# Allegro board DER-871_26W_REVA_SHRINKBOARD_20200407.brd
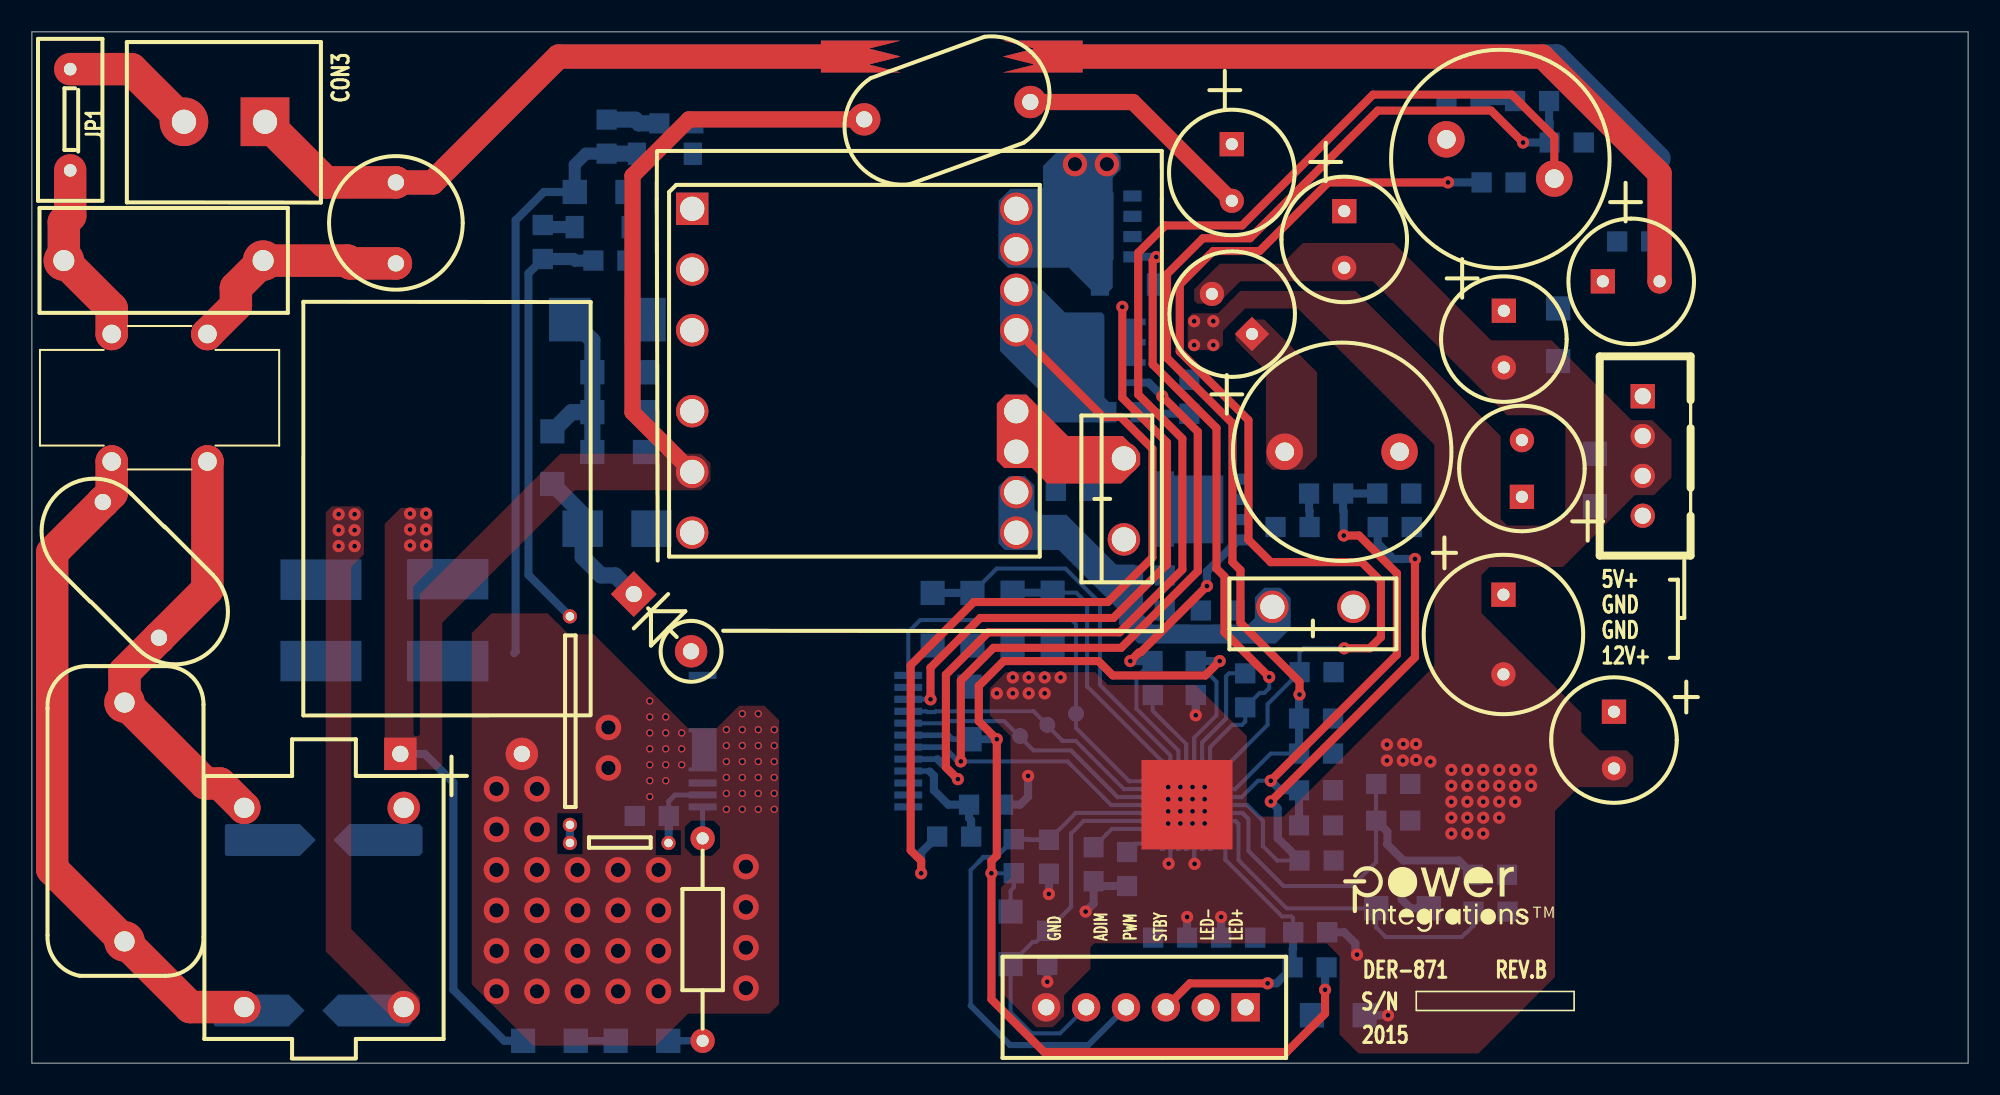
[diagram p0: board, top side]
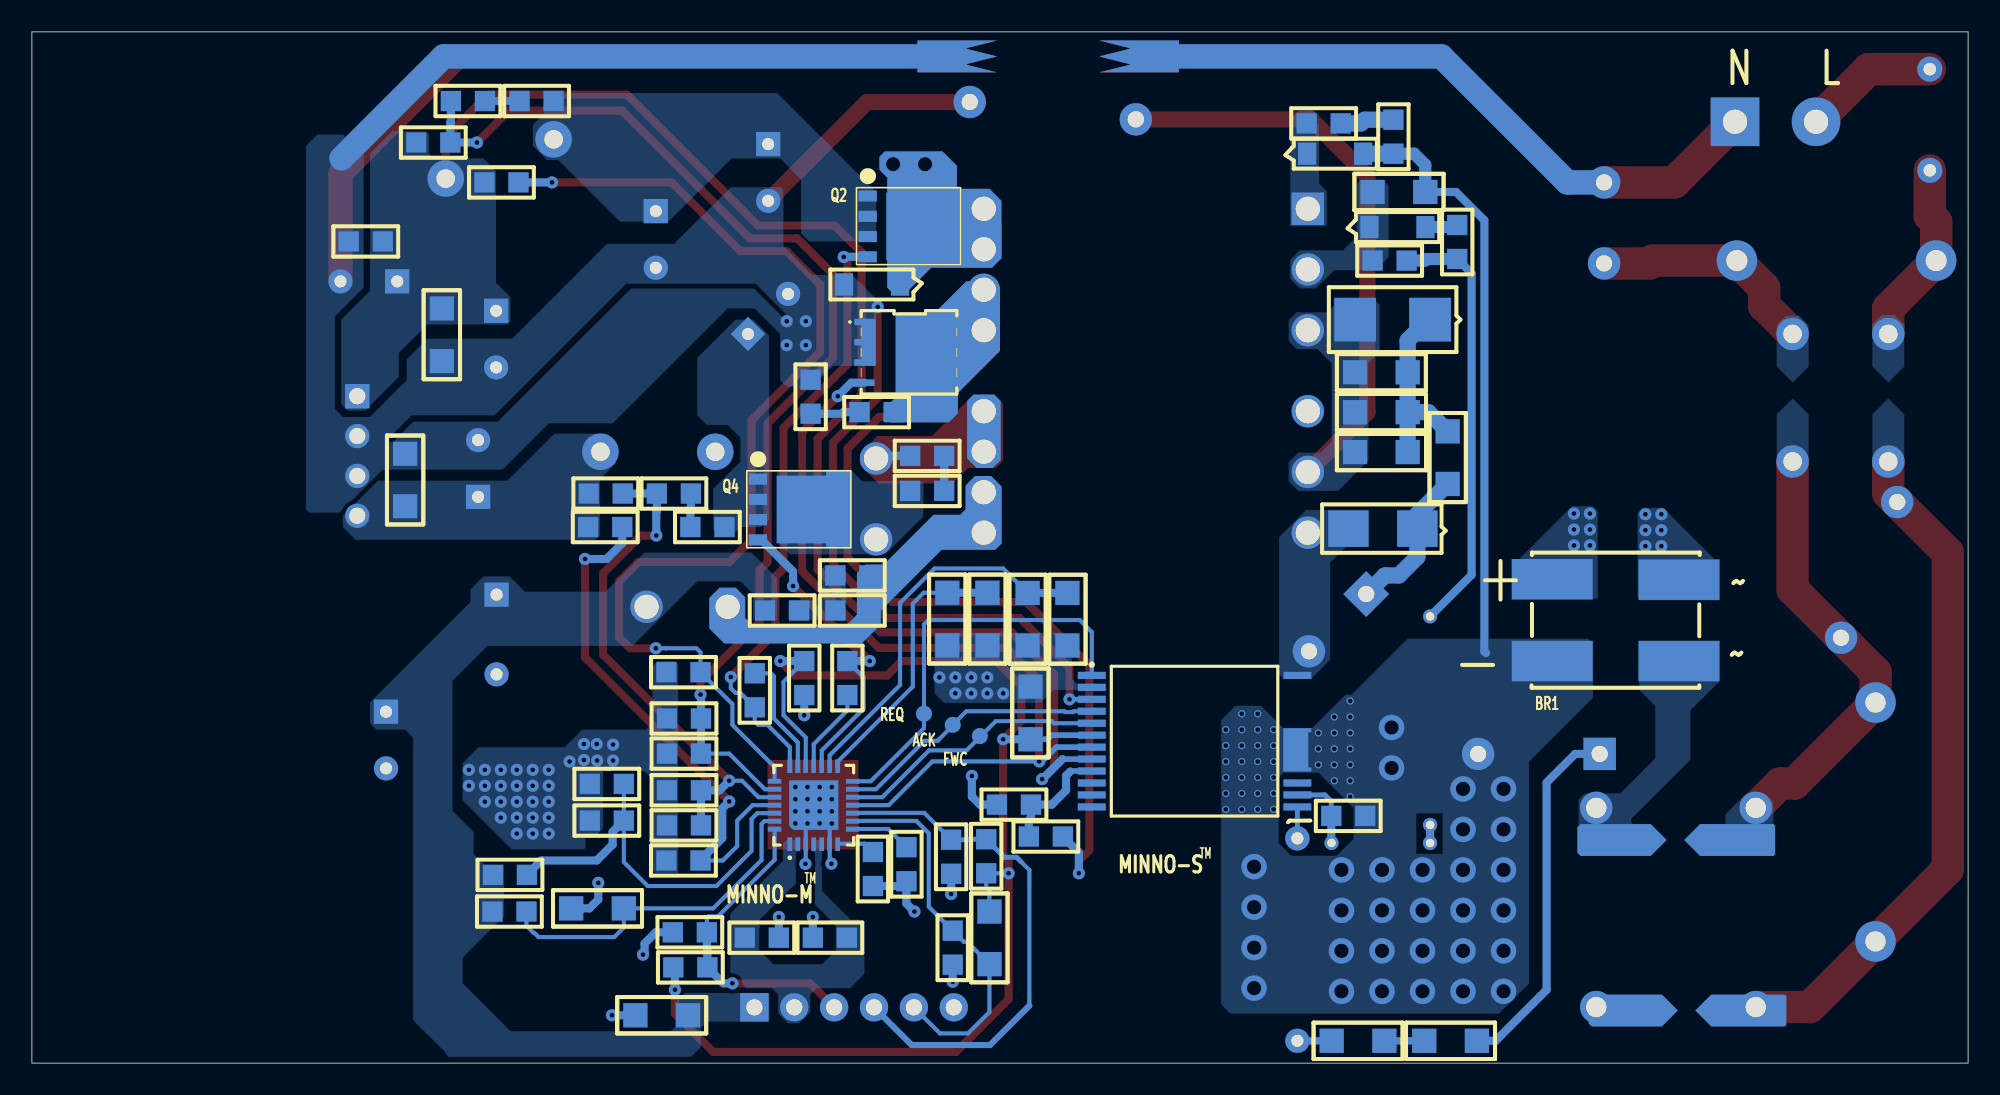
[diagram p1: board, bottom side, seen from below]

Outline 121.4 x 64.7 mm; copper layers: TOP, BOTTOM. Coordinates in mm from the lower left corner of the outline.
Outline path: 0,64.7 0,0 121.4,0 121.4,64.7 0,64.7

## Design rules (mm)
constraint set DEFAULT: min track width 0.1

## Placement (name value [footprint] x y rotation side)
BR1  Z4DGP408L-HF  [PI_SM_D_Z4D]  26.13 30.33 90 bottom
C1  22 uF  [PISMC1206]  37.34 54.65 180 bottom
C2  4.7 uF  [PISMC0805]  39.93 15.51 180 bottom
C3  100 uF  [PIPOLCAPCLYD630LS300040]  23.1 19.4 0 bottom
C4  220 nF  [PISMC0805]  76.08 22.32 90 bottom
C5  220 nF  [PISMC0805]  66.57 11.41 90 bottom
C6  0.47 nF  [PINPYCAPRAD540X290LS400040]  62.6 60.3 200 top
C7  2.2 uF  [PISMC1206]  58.79 20.32 90 bottom
C9  100 pf  [PISMC0805]  73.29 28.4 0 bottom
C10  1000 uF  [PIPOLCAPCLYD320LS140030]  75.24 57.66 270 top
C11  2.2 uF  [PISMC0805]  72.97 25.23 270 bottom
C12  DNF  [PISMC0805]  64.2 35.9 0 bottom
C13  470 uF  [PIPOLCAPCLYD320LS140030]  76.5 45.75 135 top
C14  56 uF  [PIPOLCAPCYLD10D14H5LS030]  92.27 29.39 270 top
C15  120 uF  [PIPOLCAPCLYD320LS140030]  99.2 22.05 270 top
C17  330 nF  [PINPCAPRAD760X380590050]  5.81 22.62 270 top
C18  DNF  [PISMC1206]  38.44 38.34 180 bottom
C19  DNF  [PISMC0805]  72.57 40.74 90 bottom
C25  1000 uF  [PIPOLCAPCLYD320LS140030]  82.28 53.45 270 top
C26  1000 uF  [PIPOLCAPCLYD320LS140030]  92.29 47.2 270 top
C27  470 nF  [PISMC0805]  92.99 60.36 0 bottom
C28  100 nF  [PISMC1206]  95.7 47.35 270 bottom
C29  100 nF  [PISMC1206]  80.26 3 0 bottom
C30  100 nF  [PISMC0805]  79.48 12.71 0 bottom
C31  100 nF  [PISMC0805]  79.48 24.52 0 bottom
C32  DNF  [PISMC0805]  36.04 57.06 90 bottom
C33  220 nF  [PISMC0805]  70.27 25.23 270 bottom
C34  100 nF  [PISMC1206]  98 34.94 90 bottom
C35  680 uF  [PIPOLCAPCLYD320LS140030]  93.42 35.53 90 top
C36  100 nF  [PISMC1206]  84.29 9.71 0 bottom
C37  DNF  [PISMC0805]  58.76 16.22 0 bottom
C38  DNF  [PISMC0805]  76.7 7.87 180 bottom
C39  470 nF  [PISMC0805]  80.08 35.74 0 bottom
C40  DNF  [PISMC0805]  70.3 7.87 0 bottom
C41  DNF  [PINPXCAPRAD610X260492040]  2 50.35 0 top
C44  1000 uF  [PIPOLCAPCLYD320LS140030]  98.5 49.05 0 top
C45  4.7 nF  [PISMC1206]  56.47 26.2 90 bottom
C46  DNF  [PISMC1206]  64 26.21 90 bottom
CON3  TERMINAL BLOCK  [PI_TERM_BLOCK_2PIN]  14.61 59.06 90 top
D1  BAT46W-TP  [PI_SM_SOD-123_12]  41.44 57.06 180 bottom
D2  DNF  [PISMDO214AC12]  34.53 33.53 0 bottom
D3  DST5200  [PIDVT0220ACREVA]  77.78 28.63 0 top
D4  MMSZ5252BT1G  [PI_SM_SOD-123_12]  66.97 48.85 0 bottom
D5  VS-8TQ080PBF  [PIDVT0220ACREVA]  68.47 37.94 270 top
D8  MMSZ5246B-7-F  [PI_SM_SOD-123_12]  37.54 52.45 180 bottom
D9  BYV26C  [PIDV200X150X040SOD57R]  37.74 29.43 315 top
F1  2 A  [PI_TR5_SUBMIN_FUSE]  22.82 55.26 270 top
J1  CON4  [PI_HIROSE_2P5_4POS]  101 41.84 270 top
J2  CON6  [PIHDR6PINDF125MM]  76.1 3.5 90 top
JP2  J  [PI_JUMPER200]  34.83 13.81 0 top
JP3  J  [PI_JUMPER200#2]  33.73 28.03 270 top
L1  6.8 mH  [PIIND4P_21X15MMD040]  13.31 16.02 270 top
L2  10 uH  [PI_CHOKE_H625XD539LS290D046]  88.69 57.96 340 top
L3  10 uH  [PI_CHOKE_H625XD539LS290D046]  78.55 38.36 0 top
L4  1 mH  [PIIND4PKEMET_SC-GS]  5 45.75 270 top
NOREF  -  []  82.24 12.79 0 top
NOREF#2  -  []  104.4 0 90 top
NOREF#3  -  []  0 64.7 0 top
Q1  SQJA62EP-T1_GE3  [PISMPQFN5X6B]  69.2 46.5 270 bottom
Q2  SI4154DY-T1-GE3  [PI_SM_SOT669]  69 54.4 270 bottom
Q4  SI4154DY-T1-GE3  [PI_SM_SOT669]  75.88 36.64 270 bottom
R1  10  [PISMR1206]  32.63 36.34 90 bottom
R2  DNF  [PISMR1206]  38.44 40.84 180 bottom
R3  9.1 k  [PISMR0805]  68.67 11.11 90 bottom
R4  10 k  [PISMR1206]  58.97 26.2 90 bottom
R5  47  [PISMR0805]  56.76 14.21 0 bottom
R6  DNF  [PISMR0805]  67.37 40.84 0 bottom
R7  120 k  [PISMR0805]  92.49 11.81 180 bottom
R8  3.3 k  [PISMR0805]  84.29 15.22 0 bottom
R9  10 k  [PISMR0805]  88.69 60.36 0 bottom
R10  3.3 k  [PISMR0805]  81.58 19.42 180 bottom
R11  2.00 M  [PISMR1206]  36.6 1.4 0 bottom
R12  10  [PIRAD400X175LS250031]  2.4 62.36 270 top
R13  22  [PISMR0805]  68.89 28.4 0 bottom
R14  10 k  [PISMR0805]  37.34 50.35 180 bottom
R15  DNF  [PISMR0805]  66.33 38.1 180 bottom
R16  2.00 M  [PISMR1206]  30.8 1.4 0 bottom
R17  100 k  [PISMR0805]  63.76 14.01 270 bottom
R19  100 k  [PISMR0805]  79.08 8.21 0 bottom
R22  100 k  [PISMR0805]  63.66 8.31 270 bottom
R29  DNF  [PISMR0805]  61.56 11.91 90 bottom
R35  10 k  [PISMR0805]  97.3 57.76 180 bottom
R37  47  [PISMR0805]  32.03 50.45 90 bottom
R39  DNF  [PISMR0805]  39.34 58.96 0 bottom
R40  39 k  [PISMR1206]  61.49 26.21 90 bottom
R41  3.9 k  [PISMR0805]  81.58 17.12 180 bottom
R42  33 k  [PISMR0805]  86.49 35.74 180 bottom
R44  33 k  [PISMR0805]  77.98 33.63 0 bottom
R46  DNF  [PISMR0805]  81.18 6.01 180 bottom
R47  10  [PISMR0805]  90.39 9.51 0 bottom
R48  10  [PISMR0805]  90.89 55.26 0 bottom
R49  10  [PISMR0805]  84.38 33.63 0 bottom
R50  DNF  [PISMR1206]  61.36 9.51 270 bottom
R51  4.7 k  [PISMR0805]  99.4 51.55 0 bottom
R52  DNF  [PISMR1206]  38.44 43.34 180 bottom
R53  22  [PISMR0805]  68.89 30.6 0 bottom
R54  68 k  [PISMR0805]  81.58 21.62 180 bottom
R55  68 k  [PISMR0805]  81.58 14.92 180 bottom
R56  220 k  [PISMR0805]  84.29 17.52 0 bottom
R60  0R  [PI14WRESD100LS500D030]  42.06 14.1 270 top
T1  PQ20/16  [PI_BOBBIN_PQ2016_V_14P_8X6A]  41.4 53.6 0 top
U2  MINNO (A)  [PI_IC_INSOP_24D]  54.95 24.33 180 bottom
U3  MINNO (B)  [QFN50P500X500X80-29N]  72.38 16.18 90 bottom
VDR1  275 Vac  [PIDISC500X225LS335X140040]  4.45 35.2 315 top
VR1  SMBJ150A  [PISMDO214AA12]  33.73 46.65 0 bottom

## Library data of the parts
BR1 = DISCRETE BRIDGE_+~~-
C1 C2 C4 C5 C7 C9 C11 C12 C17 C18 C27-C34 C36-C41 C45 C46 = CAP NP
C3 = CAP POL: alternate symbols: (pipolcapd630ls3000401600lhoriz)
C6 = CAP NP: alternate symbols: (pinpycaprad540x290ls400040h,pinpycaprad500x220ls400040)
C10 C25 C44 = CAP POL
C13 C26 = CAP POL: alternate symbols: (pipolcapclyd320ls140030430h)
C14 = CAP POL: alternate symbols: (pipolcapcyld10D14H5LS030H)
C15 = CAP POL: alternate symbols: (pipolcapclyd8X21P5X3P5LS30h)
C19 = CAP NP: alternate symbols: (pismc0805_1)
C35 = CAP POL: alternate symbols: (pipolcapclyd320ls140d30h750)
CON3 = CON2
D1 D4 D8 VR1 = DIODE_ZENER
D2 = DIODE
D3 D5 = DIODE SCHOTTKY
D9 = DIODE: alternate symbols: (pidax425x150040sod57,pidv200x150x040sod57r)
F1 = FUSE
J1 = CON4
J2 = CON6
JP2 JP3 = JUMPER_1
L1 = CMC_ 4P_14_23
L2 L3 = INDUCTOR
L4 = CMC_ 4P_12_43
Q1 = FET_N_SGD_123_4_5678
Q2 Q4 = FET_N_SGD_123_4_5: alternate symbols: (pismso8)
R1-R11 R13-R17 R19 R22 R29 R35 R37 R39-R42 R44 R46-R56 = R
R12 = THERMISTOR: alternate symbols: (pirad400x175ls250040_h)
R60 = R: alternate symbols: (pi14wvresd100ls125d030,pi14wvresd100ls150d030,pi14wvresd100ls200d030,pi14wvresd100ls300d030,pi14wresd100ls400d030,pi14wresd100ls500d030)
T1 = BPQ2016_14P_6-8-GENERIC
U2 = MinnoPriSec: alternate symbols: (pi_ic_insop_24d)
U3 = MINNO_Master_QFN_RevB: alternate symbols: (QFN50P500X500X80-29NTH2)
VDR1 = VARISTOR

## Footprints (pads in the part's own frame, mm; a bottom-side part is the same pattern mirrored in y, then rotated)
PI14WRESD100LS500D030
  round 1.524 hole 0.762: 1(0,0) 2(12.7,0)
PI_BOBBIN_PQ2016_V_14P_8X6A
  rect 2.032x2.032 hole 1.524: 1(0,0)
  round 2.032 hole 1.524: 2(0,-3.81) 3(0,-7.62) 4(0,-12.7) 5(0,-16.51) 6(0,-20.32) 7(20.32,-20.32) 8(20.32,-17.78) 9(20.32,-15.24) 10(20.32,-12.7) 11(20.32,-7.62) 12(20.32,-5.08) 13(20.32,-2.54) 14(20.32,0)
PI_CHOKE_H625XD539LS290D046
  round 2.286 hole 1.168: 1(0,0) 2(7.2,0)
PI_HIROSE_2P5_4POS
  rect 1.524x1.524 hole 1.016: 1(0,0)
  round 1.524 hole 1.016: 2(2.5,0) 3(5,0) 4(7.5,0)
PI_IC_INSOP_24D
  rect 1.75x0.45 smd: 1(0,0) 2(0,-0.75) 3(0,-1.5) 4(0,-2.25) 5(0,-3) 6(0,-3.75) 7(0,-4.5) 8(0,-5.25) 9(0,-6) 10(0,-6.75) 11(0,-7.5) 12(0,-8.25) 13(12.89,-8.25) 14(12.89,-7.5) 15(12.89,-6.75) 24(12.89,0)
  custom 0.44x0.44 smd: 16(12.89,-4.67)
PI_JUMPER200
  round 0.889 hole 0.533: 1(-1.1,0) 2(5.08,0)
PI_JUMPER200#2
  round 0.889 hole 0.533: 1(0,0) 2(13.08,0)
PI_SM_D_Z4D
  rect 2.54x5.08 smd: 1(0.025,-0.051) 2(0,-8.001) 3(-5.105,-8.001) 4(-5.105,-0.051)
PI_SM_SOD-123_12
  rect 1.14x1.4 smd: 1(0,0) 2(3.51,0)
PI_SM_SOT669
  rect 0.7x1.15 smd: 1(0,0) 2(1.27,0) 3(2.54,0) 4(3.81,0)
  rect 4.7x1.5 smd: 5(1.875,5.025)
PI_TERM_BLOCK_2PIN
  rect 3.05x3.05 hole 1.52: 1(0,0)
  round 3.05 hole 1.52: 2(0,5.08)
PI_TR5_SUBMIN_FUSE
  round 2.03 hole 1.02: 1(0,0) 2(5.08,0)
PIDISC500X225LS335X140040
  round 2.03 hole 1.02: 1(0,0) 2(8.509,-3.531)
PIDV200X150X040SOD57R
  rect 2.032x2.032 hole 1.016: 1(0,0)
  round 2.032 hole 1.016: 2(5.08,0)
PIDVT0220ACREVA
  round 2.032 hole 1.524: 1(5.08,0) 2(0,0)
PIHDR6PINDF125MM
  rect 1.778x1.778 hole 1.016: 1(0,0)
  round 1.778 hole 1.016: 2(0,2.499) 3(0,5.001) 4(0,7.501) 5(0,10) 6(0,12.502)
PIIND4P_21X15MMD040
  round 2.032 hole 1.27: 1(0,0) 2(12.5,0) 3(12.5,10) 4(0,10)
PIIND4PKEMET_SC-GS
  round 2.032 hole 1.168: 1(0,0) 2(8,0) 3(8,6) 4(0,6)
PINPCAPRAD760X380590050
  round 2.54 hole 1.27: 1(0,0) 2(14.986,0)
PINPXCAPRAD610X260492040
  round 2.54 hole 1.32: 1(0,0) 2(12.497,0)
PINPYCAPRAD540X290LS400040
  round 2.03 hole 1.02: 1(0,0) 2(10.16,-2.54)
PIPOLCAPCLYD320LS140030
  rect 1.52x1.52 hole 0.76: 1(0,0)
  round 1.52 hole 0.76: 2(3.556,0)
PIPOLCAPCLYD630LS300040
  rect 2.03x2.03 hole 1.02: 1(0,0)
  round 2.03 hole 1.02: 2(7.62,0)
PIPOLCAPCYLD10D14H5LS030
  rect 1.52x1.52 hole 0.76: 1(0,0)
  round 1.52 hole 0.76: 2(5,0)
PIRAD400X175LS250031
  round 1.58 hole 0.79: 1(0,0) 2(6.35,0)
PISMC0805
  rect 1.27x1.27 smd: 1(0,0) 2(2.134,0)
PISMC1206
  rect 1.52x1.52 smd: 1(0,0) 2(3.3,0)
PISMDO214AA12
  rect 2.62x2.74 smd: 1(0,0) 2(4.699,0)
PISMDO214AC12
  rect 2.54x2.29 smd: 1(0,0) 2(4.32,0)
PISMPQFN5X6B
  rect 0.406x1.27 smd: 1(0,0) 2(1.27,0) 3(2.54,0) 4(3.81,0)
  rect 0.406x1.219 smd: 5(3.81,5.588) 6(2.54,5.588) 7(1.27,5.588) 8(0,5.588)
PISMR0805
  rect 1.27x1.27 smd: 1(0,0) 2(2.134,0)
PISMR1206
  rect 1.52x1.52 smd: 1(0,0) 2(3.3,0)
QFN50P500X500X80-29N
  rect 0.85x0.3 smd: 1(-2.45,1.5) 2(-2.45,1) 3(-2.45,0.5) 4(-2.45,0) 5(-2.45,-0.5) 6(-2.45,-1) 7(-2.45,-1.5) 15(2.45,-1.5) 16(2.45,-1) 17(2.45,-0.5) 18(2.45,0) 19(2.45,0.5) 20(2.45,1) 21(2.45,1.5)
  rect 0.3x0.85 smd: 8(-1.5,-2.45) 9(-1,-2.45) 10(-0.5,-2.45) 11(0,-2.45) 12(0.5,-2.45) 13(1,-2.45) 14(1.5,-2.45) 22(1.5,2.45) 23(1,2.45) 24(0.5,2.45) 25(0,2.45) 26(-0.5,2.45) 27(-1,2.45) 28(-1.5,2.45)
  custom 0.773x0.773 smd: EP(0,0)

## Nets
GND POWER: C5.1 C6.1 C7.2 C10.2 C11.2 C13.2 C14.2 C15.2 C19.2 C25.2 C26.2 C28.2 C29.2 C30.2 C31.2 C34.2 C35.2 C36.2 C37.2 C38.2 C40.2 C44.2 C45.1 C46.1 D4.2 J1.2 J1.3 J2.6 Q1.1 Q1.2 Q1.3(S3) R3.1 R4.1 R8.2 R10.1 R17.2 R19.2 R22.2 R40.1 R41.1 R51.2 R54.1 R55.1 R56.2 U2.2 U2.3 U3.3 U3.6 U3.EP
VIN_DC+: BR1.1 C3.1 C6.2 C18.1 R2.1 R16.1 R52.1 T1.3 T1.5 VR1.2
VIN_DC-: BR1.4 C1.2 C2.2 C3.2 C32.1 D1.2 U2.16
+V_CV1: C26.1 C28.1 C44.1 J1.1 L2.2 R35.1 R48.2 R51.1 U2.8(VOUT)
+V_CV1_PRE: C10.1 C25.1 L2.1 Q2.1 Q2.2 Q2.3(S3) R9.1
+V_CV2: C34.1 C35.1 J1.4 L3.2 R42.1 R49.2
+V_CV2_PRE: C12.2 D5.1 Q4.5
+V_LED: C9.2 C14.1 C15.1 C29.1 D3.1 J2.1 R7.1 R47.2
ADIM: J2.5 R22.1 R50.2 U3.9
BIAS_1_TX: C1.1 D8.1 R14.1 T1.2
BIAS_2_TX: D1.1 R39.2 T1.1
BP5V: C7.1 C11.1 R29.1 R46.1 R50.1 U2.6 U3.19
CV1_TX: D4.1 Q2.5 T1.13
CV2_TX: D5.2 R15.1 T1.9
D1_TX: D2.2 D9.2 T1.6 U2.24
GDR1: C4.1 Q2.4 U3.21
GDR2: C33.1 Q4.4 U3.17
LED_RTN: C38.1 C40.1 J2.2 U3.1 U3.2 U3.4 U3.5
LED_TX: D3.2 R13.1 R53.1 T1.7
LINE: CON3.2 R12.1
LN_IN_1: C17.2 L1.2 L4.2 VDR1.1
LN_IN_2: BR1.2 L1.3
LN_IN_3: BR1.3(AC2) L1.4
LN_IN_4: C17.1 L1.1 L4.3 VDR1.2
NEUTRAL: CON3.1 F1.1
PWM: J2.4 R17.1 R29.2 U3.10
SR_D: Q1.5 Q1.6 Q1.7 Q1.8 R5.1 R6.1 T1.11
SR_GDR: Q1.4 U2.7 U3.11
STDBY: J2.3 R19.1 R46.2 U3.28
N265348: C18.2 R1.2 R2.2 R52.2 VR1.1
N265875: JP3.1 R14.2 R37.1
N265882: D8.2 R37.2
N266437: C2.1 JP2.2 U2.14
N266812: R60.1 U2.13
N268540: U2.4 U3.13
N269745: R7.2 R8.1 R56.1 U3.26
N276717: C4.2 U3.20
N282159: C12.1 R15.2
N282590: C37.1 R5.2 U2.9
N291571: U2.5 U3.12
N348677: D2.1 D9.1 R1.1
N383807: C27.2 R10.2 R35.2 R54.2 U3.23
N496691: C32.2 R39.1
N515201: C13.1 L3.1 Q4.1 Q4.2 Q4.3(S3) R44.1
N529887: U2.1 U3.14
N563406: C9.1 R13.2 R53.2
N641623: R11.1 R16.2
N641634: R11.2 R60.2
N670571: C39.2 R41.2 R42.2 R55.2 U3.24
N670621: C27.1 R9.2
N670685: C39.1 R44.2
N707266: C41.2 F1.2 L4.4
N707302: C41.1 L4.1 R12.2
N797298: C19.1 R6.2
N16752139: C45.2 R4.2 U3.16
N16752147: C46.2 R40.2 U3.15
N16752545: C31.1 R48.1 U3.22
N16752942: C33.2 U3.18
N16753892: C30.1 R49.1 U3.25
N16755678: C36.1 R47.1 U3.27(VCV3)
N16756663: R3.2 U3.7
N16756996: C5.2 U3.8
N16782134: JP2.1 JP3.2

Pads without a net: T1 4 8 10 12 14; U2 10 11 12 15

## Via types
v1: diameter 0.762, hole 0.305, TOP to BOTTOM, 106 vias
v2: diameter 1.524, hole 0.889, TOP to BOTTOM, 2 vias
v3: diameter 1.6, hole 0.9, TOP to BOTTOM, 30 vias
v4: diameter 0.457, hole 0.305, TOP to BOTTOM, 41 vias

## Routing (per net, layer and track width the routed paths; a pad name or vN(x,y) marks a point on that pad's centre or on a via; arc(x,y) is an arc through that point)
GND POWER: length 172.2
  TOP w0.1: v1(86.79,20.02) 86.89,20.02
  TOP w0.508: v1(68.37,47.45) 68.37,41.74 71.17,38.94 71.17,31.29 67.81,27.93 59.46,27.93 56.34,24.81 v1(56.34,22.82)
  TOP w1.016: C6.1 69.04,60.3 C10.2
  TOP w1.5: 63.42,63.1 63.37,63.15
  TOP w1.524: 63.37,63.15 94.71,63.15 102.05,55.81 C44.2
  BOTTOM w0.254: v1(71.27,12.51) 71.38,12.62 U3.6 71.38,15.18 U3.EP 72.88,15.68 U3.3 72.88,12.52 v1(72.9,12.5)
  BOTTOM w0.305: U2.3 v1(56.34,22.82)
  BOTTOM w0.508: R3.1 66.87,11.11 C5.1 66.57,10.01 v1(66.07,9.51) ; v1(62.46,18.02) 62.46,16.72 61.96,16.22 C37.2 ; C38.2 v1(74.57,9.17) ; C36.2 86.44,9.71 85.89,10.26 v1(85.89,11.31) ; R19.2 82.28,8.21 82.98,7.51 82.98,6.91 v1(83.08,6.81) ; C40.2 v1(72.43,9.17) ; C29.2 v1(85.03,3) ; R22.2 v1(63.66,5.11) ; C11.2 v1(72.97,21.82) ; R17.2 v1(63.76,10.61)
  BOTTOM w1.524: 101.99,56.76 95.59,63.16 63.38,63.16
  vias: v1(60.5,23.2) v1(61.5,24.2) v1(61.5,23.2) v1(62.5,24.2) v1(62.5,23.2) v1(63.5,24.2) v1(63.5,23.2) v1(64.5,24.2) v1(71.25,17.32) v1(71.25,16.56) v1(71.25,15.79) v1(71.25,15.03) v1(72.01,17.32) v1(72.01,16.56) v1(72.01,15.8) v1(72.01,15.04) v1(72.77,17.32) v1(72.77,16.56) v1(72.77,15.8) v1(72.77,15.04) v1(72.87,46.55) v1(72.87,45.05) v1(73.53,17.32) v1(73.53,16.56) v1(73.53,15.8) v1(73.53,15.04) v1(74.07,46.55) v1(74.07,45.05) v1(84.96,19.98) v1(84.96,18.98) v1(85.99,20.02) v1(85.96,18.98) v1(86.79,19.02) v1(87.69,18.92) v1(89,18.4) v1(89,17.4) v1(89,16.4) v1(89,15.4) v1(89,14.4) v1(90,18.4) v1(90,17.4) v1(90,16.4) v1(90,15.4) v1(90,14.4) v1(91,18.4) v1(91,17.4) v1(91,16.4) v1(91,15.4) v1(91,14.4) v1(92,18.4) v1(92,17.4) v1(92,16.4) v1(92,15.4) v1(93,18.4) v1(93,17.4) v1(93,16.4) v1(94,18.4) v1(94,17.4)
VIN_DC+: length 58.9
  TOP w1.016: C6.2 41.2,59.21 37.66,55.67 37.66,40.83 T1.5
  BOTTOM w0.508: C3.1 24.63,19.4 26.43,17.61 26.43,4.6 29.62,1.4 R16.1
  vias: v1(23.71,34.48) v1(23.71,33.48) v1(23.71,32.48) v1(24.71,34.48) v1(24.71,33.48) v1(24.71,32.48)
VIN_DC-: length 37.5
  BOTTOM w0.508: 30.23,25.73 30.33,25.83 30.33,52.88 32.1,54.65 C1.2
  BOTTOM w0.762: C32.1 34.73,57.06 34.04,56.36 C1.2
  BOTTOM w1.016: C32.1 D1.2
  vias: v3(29.13,17.2) v3(29.13,14.66) v3(29.13,12.12) v3(29.13,9.58) v3(29.13,7.04) v3(29.13,4.5) v3(31.67,17.2) v3(31.67,14.66) v3(31.67,12.12) v3(31.67,9.58) v3(31.67,7.04) v3(31.67,4.5) v3(34.21,12.12) v3(34.21,9.58) v3(34.21,7.04) v3(34.21,4.5) v3(36.15,21.06) v3(36.15,18.52) v3(36.75,12.12) v3(36.75,9.58) v3(36.75,7.04) v3(36.75,4.5) v3(39.29,12.12) v3(39.29,9.58) v3(39.29,7.04) v3(39.29,4.5) v3(44.77,12.32) v3(44.77,9.78) v3(44.77,7.24) v3(44.77,4.7) v4(38.74,22.72) v4(38.74,21.72) v4(38.74,20.72) v4(38.74,19.72) v4(38.74,18.72) v4(38.74,17.72) v4(38.74,16.72) v4(39.74,21.72) v4(39.74,20.72) v4(39.74,19.72) v4(39.74,18.72) v4(39.74,17.72) v4(40.74,20.72) v4(40.74,19.72) v4(40.74,18.72) v4(43.54,20.92) v4(43.54,19.92) v4(43.54,18.92) v4(43.54,17.92) v4(43.54,16.92) v4(43.54,15.92) v4(44.54,21.92) v4(44.54,20.92) v4(44.54,19.92) v4(44.54,18.92) v4(44.54,17.92) v4(44.54,16.92) v4(44.54,15.92) v4(45.54,21.92) v4(45.54,20.92) v4(45.54,19.92) v4(45.54,18.92) v4(45.54,17.92) v4(45.54,16.92) v4(45.54,15.92) v4(46.54,20.92) v4(46.54,19.92) v4(46.54,18.92) v4(46.54,17.92) v4(46.54,16.92) v4(46.54,15.92)
+V_CV1: length 83
  TOP w0.508: v1(58.06,17.82) 57.31,18.57 57.31,24.37 59.96,27.03 68.2,27.03 72.14,30.97 72.14,39.18 69.37,41.94 69.37,50.85 71.07,52.55 75.88,52.55 84.08,60.76 92.79,60.76 95.45,58.1 L2.2
  BOTTOM w0.35: U2.8 54.95,19.07 56.78,19.07
  BOTTOM w0.508: 56.78,19.07 57.94,17.92 57.96,17.92 v1(58.06,17.82)
ADIM: length 24
  BOTTOM w0.254: U3.9 69.92,15.2 65.95,15.2 65.17,14.42 65.17,9.81 R22.1 62.96,7.61 62.76,7.61 R50.2 61.36,3.2 62.7,1.87 64.47,1.87 J2.5
BP5V: length 81.8
  TOP w0.508: v1(74.48,25.23) 73.57,24.32 67.77,24.32 66.87,25.23 60.93,25.23 59.37,23.66 59.37,21.45 v1(60.5,20.32) 60.5,13.02 60.16,12.68 v1(60.16,11.91) 60.16,4 63.46,0.7 78.68,0.7 81.08,3.1 v1(81.08,4.6)
  BOTTOM w0.254: C11.1 74.27,23.92 74.27,21.82 72.88,20.43 U3.19 ; v1(60.16,11.91) R29.1 61.56,11.02 61.36,10.82 R50.1
  BOTTOM w0.35: U2.6 57.47,20.57 57.73,20.32 C7.1
  BOTTOM w0.5: v1(60.5,20.32) C7.1
  BOTTOM w0.508: v1(81.08,4.6) 81.08,5.91 R46.1 ; C11.1 v1(74.48,25.23)
CV1_TX:
  vias: v2(65.4,56.4) v2(67.4,56.4)
CV2_TX: length 2.2
  BOTTOM w0.508: R15.1 68.31,38.1 D5.2
GDR1: length 38.6
  TOP w0.508: v1(77.58,24.22) 74.77,27.03 74.77,30.53 74.27,31.03 74.27,39.84 70.27,43.84 70.27,50.35 v1(70.5,50.58)
  BOTTOM w0.254: v1(77.58,24.22) 77.58,23.52 77.28,23.22 76.98,23.22 C4.1 76.08,21.43 75.87,21.22 75.28,21.22 73.88,19.83 U3.21
  BOTTOM w0.508: v1(70.5,50.58) 70.49,50.59 Q2.4
GDR2: length 20.2
  TOP w0.508: v1(73.67,29.93) 69.51,25.77 69.41,25.77 v1(68.87,25.23)
  BOTTOM w0.254: C33.1 69.25,24.21 69.25,22.24 71.88,19.61 U3.17
  BOTTOM w0.508: v1(73.67,29.93) 73.67,30.85 75.65,32.83 Q4.4 ; C33.1 v1(68.87,25.23)
LINE: length 8.5
  TOP w2.032: CON3.2 6.23,62.36 R12.1
LN_IN_1: length 42.7
  TOP w2.032: L4.2 5,35.76 VDR1.1 1.27,32.03 1.27,12.17 C17.2 9.93,3.52 L1.2
LN_IN_2:
  vias: v1(19.23,34.43) v1(19.23,33.43) v1(19.23,32.43) v1(20.23,34.43) v1(20.23,33.43) v1(20.23,32.43)
LN_IN_4: length 27.5
  TOP w2.032: L4.3 11.01,37.75 11.01,29.73 VDR1.2 5.81,24.53 C17.1 10.88,17.54 11.78,17.54 L1.1
NEUTRAL: length 74.6
  TOP w1.524: F1.1 25.13,55.26 33.02,63.15 51.97,63.15
  TOP w2.032: CON3.1 18.42,55.26 F1.1
  BOTTOM w1.524: F1.1 25.13,55.26 33.03,63.16 51.98,63.16
PWM: length 32.8
  BOTTOM w0.254: 58.86,3.6 58.86,12.11 59.38,12.63 ; U3.10 69.91,15.7 65.45,15.7 R17.1
  BOTTOM w0.305: R17.1 62.51,14.01 62.48,14.05 R29.2 60.43,12.91 59.66,12.91 59.38,12.63
  BOTTOM w0.381: J2.4 66.23,1.13 61.33,1.13 58.86,3.6
SR_D: length 52.4
  TOP w0.508: T1.11 67.16,40.54 68.27,40.54 70.26,38.55 70.26,31.72 67.46,28.93 59.06,28.93 55.1,24.97 55.1,13.35 55.76,12.7 v1(55.76,11.91)
  BOTTOM w0.508: R5.1 55.76,13.21 v1(55.76,11.91)
SR_GDR: length 53.2
  TOP w0.508: v1(58.24,18.93) 58.24,24.01 60.29,26.05 68.3,26.05 73.1,30.86 73.1,39.61 v1(70.87,41.84)
  BOTTOM w0.254: U3.11 67.68,16.18 67.23,16.63 64.93,18.93 v1(58.24,18.93)
  BOTTOM w0.35: U2.7 57.17,19.83 58.06,18.93 v1(58.24,18.93)
  BOTTOM w0.508: Q1.4 70.02,42.69 v1(70.87,41.84)
STDBY: length 19.8
  TOP w0.508: v1(77.48,5.01) 72.6,5.01 J2.3
  BOTTOM w0.254: U3.28 74.83,12.76 78.38,9.21 78.97,9.21 79.08,9.1 R19.1
  BOTTOM w0.508: v1(77.48,5.01) 78.05,5.01 R46.2 79.05,7.16 79.08,7.19 R19.1
N265348: length 12
  BOTTOM w1.016: R2.2 R52.2 35.14,45.34 33.83,46.65 VR1.1 ; R2.2 33.84,40.84 R1.2 ; R2.2 C18.2
N265875: length 27.1
  BOTTOM w0.508: R37.1 31.13,49.55 31.13,30.63 JP3.1
  BOTTOM w0.762: R14.2 34.06,50.35 33.96,50.45 R37.1
N265882: length 2.1
  BOTTOM w0.762: R37.2 32.16,52.45 D8.2
N266437: length 4.9
  BOTTOM w0.305: C2.1 39.93,16.43 40.33,16.83 42.06,16.83 U2.14
  BOTTOM w0.508: C2.1 39.93,13.83 JP2.2
N266812: length 2
  BOTTOM w0.305: U2.13 R60.1
N268540: length 17.1
  BOTTOM w0.254: U3.13 68.48,17.18 65.44,20.22 64.62,20.22 63.6,21.23 63.6,21.28 62.81,22.08 56.66,22.08 56.61,22.02 56.13,22.02 56.08,22.08 U2.4
N269745: length 26
  BOTTOM w0.254: U3.26 75.91,15.68 76.28,15.32 76.28,13.31 78.48,11.11 82.78,11.11 84.29,12.61 R8.1 R56.1
  BOTTOM w0.508: R7.2 89.46,12.71 85.99,12.71 84.99,13.71 84.99,14.51 R8.1
N276717: length 7.5
  BOTTOM w0.254: C4.2 75.06,24.46 74.88,24.27 74.88,21.62 73.38,20.13 U3.20
N282159: length 2.2
  BOTTOM w0.508: R15.2 C12.1
N282590: length 7.3
  BOTTOM w0.35: 56.29,18.3 56.26,18.33 U2.9
  BOTTOM w0.5: 56.56,18.03 56.29,18.3
  BOTTOM w0.508: 56.56,18.03 56.56,17.12 57.46,16.22 C37.1 58.76,16.22 58.76,15.37 58.89,15.23 R5.2
N291571: length 17
  BOTTOM w0.254: U2.5 57.33,21.33 57.46,21.46 60.96,21.46 62.8,19.62 65.14,19.62 68.08,16.68 U3.12
N348677: length 9.5
  BOTTOM w1.016: R1.1 34.53,34.43 D2.1 34.53,31.75 35.69,30.6 36.57,30.6 D9.1
N383807: length 70.8
  TOP w0.508: v1(93.49,57.76) 91.49,59.76 84.38,59.76 76.38,51.75 73.42,51.75 71.17,49.5 71.17,44.24 75.28,40.14 75.28,31.43 75.78,30.93 75.78,27.63 79.48,23.92 v1(79.48,23.12)
  BOTTOM w0.254: U3.23 75.44,17.18 77.68,19.42 R10.2
  BOTTOM w0.508: v1(79.48,23.12) 79.45,23.09 R54.2 R10.2 ; v1(93.49,57.76) R35.2 95.17,59 95.13,59.04 C27.2
N496691: length 3.4
  BOTTOM w1.016: C32.2 37.83,59.19 38.07,58.96 R39.1
N529887: length 26
  BOTTOM w0.254: U3.14 68.8,17.68 65.47,21.02 65.47,27.53 65.19,27.8 55.7,27.8 54.95,27.04 U2.1
N641623: length 2.5
  BOTTOM w0.457: R11.1 R16.2
N641634: length 2.2
  BOTTOM w0.457: R60.2 R11.2
N670571: length 32.9
  TOP w0.508: v1(77.68,17.72) 85.59,25.62 85.59,30.73 83.22,33.1 v1(82.25,33.1)
  BOTTOM w0.254: v1(77.68,17.72) 76.88,17.72 75.84,16.68 U3.24
  BOTTOM w0.508: v1(82.25,33.1) 82.25,34.6 82.21,34.64 C39.2 R42.2 ; R55.2 R41.2 78.28,17.12 v1(77.68,17.72)
N670621: length 2.2
  BOTTOM w0.508: R9.2 C27.1
N670685: length 2.1
  BOTTOM w0.508: C39.1 80.08,34.68 80.11,34.65 R44.2
N707266: length 14.4
  TOP w2.032: F1.2 19.96,50.18 19.79,50.35 C41.2 12.79,48.64 12.79,47.53 11.01,45.75 L4.4
N707302: length 11.7
  TOP w2.032: R12.2 2.4,53.17 2,52.77 C41.1 5,47.35 L4.1
N797298: length 3.1
  BOTTOM w0.508: R6.2 70.52,40.84 70.62,40.74 C19.1
N16752139: length 24.1
  BOTTOM w0.254: R4.2 60.5,31.03 64.8,31.03 66.97,28.87 66.97,23.72 71.38,19.31 U3.16
  BOTTOM w0.508: R4.2 C45.2
N16752147: length 17.1
  BOTTOM w0.254: C46.2 65.48,29.51 66.17,28.83 66.17,23.62 70.9,18.89 70.88,18.87 U3.15
  BOTTOM w0.508: C46.2 R40.2
N16752545: length 67.8
  TOP w0.508: v1(88.79,55.26) 81.28,55.26 76.98,50.95 74.07,50.95 71.97,48.85 71.97,44.64 76.28,40.34 76.28,32.83 77.68,31.43 83.38,31.43 84.58,30.23 84.58,26.73 83.88,26.03 v1(82.28,26.03)
  BOTTOM w0.254: v1(82.28,26.03) 81.64,26.03 79.73,26.03 79.48,25.77 C31.1 77.48,22.52 77.48,21.22 74.83,18.57 U3.22
  BOTTOM w0.508: R48.1 v1(88.79,55.26)
N16752942: length 5.3
  BOTTOM w0.254: U3.18 72.38,20.01 70.27,22.12 C33.2
N16753892: length 34.2
  TOP w0.508: v1(86.72,31.63) 86.72,25.46 v1(77.68,16.42)
  BOTTOM w0.254: U3.25 76.18,16.18 76.19,16.2 77.18,15.22 77.18,13.61 78.08,12.71 C30.1
  BOTTOM w0.508: R49.1 84.38,32.61 85.37,31.63 v1(86.72,31.63) ; C30.1 79.48,12.75 78.11,14.11 78.11,15.98 v1(77.68,16.42)
N16755678: length 21.8
  BOTTOM w0.254: U3.27 75.47,15.18 75.65,15.01 75.65,12.74 78.68,9.71 C36.1 84.29,8.51 84.89,7.91 89.64,7.91 89.89,8.16 89.94,8.16 90.39,8.62 R47.1
N16756663: length 2.4
  BOTTOM w0.254: R3.2 68.68,13.24 69.2,13.77 70.84,13.77 U3.7
N16756996: length 3.8
  BOTTOM w0.254: U3.8 69.92,14.69 67.71,14.69 67.38,14.36 C5.2
N16782134: length 1.1
  BOTTOM w0.508: JP3.2 33.73,14.95 JP2.1

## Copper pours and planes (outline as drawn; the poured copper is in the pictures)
GND POWER on TOP (solid shape): 74.68,13.81 70.07,13.81 70.07,18.42 74.68,18.42
GND POWER on TOP (solid shape): 75.28,13.41 69.57,13.41 69.57,19.02 75.28,19.02
GND POWER on TOP (solid shape): 65.87,62.15 60.87,62.15 62.87,62.65 60.87,63.15 62.87,63.65 60.87,64.15 65.87,64.15
GND POWER on BOTTOM (solid shape): 69.4,43.76 68.49,43.76 68.49,46.68 69.4,46.68
GND POWER on BOTTOM (solid shape): 65.88,62.16 60.88,62.16 62.88,62.66 60.88,63.16 62.88,63.66 60.88,64.16 65.88,64.16
GND POWER on TOP: outline of 84 points within 60.06,0.6 102.8,51.45
GND POWER on BOTTOM: 102.1,34.54 104.01,34.54 104.21,34.74 104.21,57.56 103.5,58.26 101.9,58.26 100.6,56.96 100.6,48.65 102.4,46.85 102.4,41.04 101.9,40.54 100.2,40.54 97.9,42.84 97.9,44.14 96.6,45.45 91.29,45.45 90.19,46.55 90.19,46.55 85.34,51.4 81.13,51.4 77.58,54.95 74.47,54.95 74.27,54.76 74.27,51.25 73.82,50.8 72.47,49.45 69.97,49.45 68.17,47.65 68.17,47.25 68.47,46.95 68.47,43.94 68.67,43.74 71.17,43.74 71.97,42.94 71.97,42.64 72.17,42.44 72.87,42.44 73.27,42.84 73.27,46.15 76.03,48.9 84.13,48.9 92.39,40.64 97.6,40.64 99,39.24 99,39.04 98.9,38.94 98.8,38.94 97.5,40.24 92.19,40.24 83.83,48.6 76.13,48.6 73.67,46.15 73.67,43.04 74.17,42.54 74.47,42.84 74.47,45.75 76.08,47.35 77.78,47.35 84.98,40.14 88.99,40.14 91.89,37.24 99.4,37.24
GND POWER on BOTTOM: 80.88,11.91 80.88,25.03 81.08,25.23 82.18,25.23 82.48,24.92 82.48,21.32 82.88,20.92 86.89,20.92 86.89,20.92 87.99,19.82 93.4,19.82 94.4,18.82 94.4,16.5 91.7,13.8 91.31,13.41 86.79,13.41 86.69,13.51 86.69,14.21 86.09,14.21 85.59,14.71 85.59,18.32 82.98,18.32 82.48,17.82 82.48,12.11 82.28,11.91
GND POWER on BOTTOM: 56.5,27 64.66,27 64.8,26.86 64.8,23.2 64.2,22.6 58.16,22.6 57.34,23.42 54.24,23.42 54.23,23.43 54.23,23.73 54.3,23.8 55.9,23.8 56.2,24.1 56.2,26.7
GND POWER on BOTTOM: 72.77,42.44 74.07,42.44 74.47,42.84 74.47,45.75 74.77,46.05 74.77,46.15 74.37,46.55 74.07,46.55 73.97,46.45 73.87,46.45 73.77,46.55 73.77,46.65 72.97,46.65 72.77,46.45
VIN_DC+ on TOP: 25.13,31.13 23.92,29.93 23.92,20.62 24.02,20.52 24.22,20.52 24.32,20.62 24.32,29.43 33.13,38.24 41.94,38.24 42.54,37.64 42.54,36.54 41.94,35.94 34.03,35.94 25.73,27.63 25.73,18.72 25.43,18.42 22.22,18.42 22.12,18.52 22.12,33.83 23.12,34.83 24.92,34.83 25.13,34.63
VIN_DC+ on BOTTOM: 23.27,29.15 28.37,29.15 28.57,29.36 28.57,31.19 24.82,34.93 23.52,34.93 23.22,34.63 23.22,29.2
VIN_DC+ on BOTTOM: 42.1,47.1 42.6,46.6 42.6,45.3 42.1,44.8 40.8,44.8 39.9,43.9 39.9,39 40.6,38.3 42,38.3 42.6,37.7 42.6,36.5 42,35.9 39.5,35.9 37.6,37.8 37.6,43.9 36.9,44.6 36.9,47.6 37.1,47.8 39.5,47.8 40.2,47.1
VIN_DC- on TOP: 27.57,26.97 28.82,28.22 32.33,28.22 33.66,26.9 35.23,26.9 39.01,23.11 40.06,22.1 41.13,21.02 42.93,21.02 44.33,22.42 45.93,22.42 46.85,21.51 46.85,15.22 41.34,15.22 40.94,14.81 40.94,13.51 41.44,13.01 42.64,13.01 43.14,13.51 43.14,14.91 46.75,14.91 46.85,14.81 46.85,3.7 46.25,3.1 41.14,3.1 39.14,1.1 31.43,1.1 27.57,4.95 ; 2 cut-outs
VIN_DC- on TOP: 42.64,15.52 46.85,15.52 46.85,14.71 43.14,14.71 43.14,14.81 42.64,15.32
VIN_DC- on BOTTOM: 29.42,3.1 27.53,5 27.53,18.91 23.52,22.91 23.52,26.33 23.82,26.63 34.93,26.63 34.93,26.62 35.14,26.62 38.65,23.12 39.03,23.12 41.13,21.02 42.93,21.02 44.33,22.42 45.93,22.42 46.84,21.52 46.84,3.69 46.25,3.1 ; 2 cut-outs
+V_CV1 on BOTTOM: 96.2,56.76 96.5,57.06 96.5,58.26 96.7,58.46 98.8,58.46 100.2,57.06 100.2,48.45 102,46.65 102,41.34 101.6,40.94 100.5,40.94 98.4,43.04 98.4,44.55 96.6,46.35 91.59,46.35 91.39,46.55 91.39,48.05 92.29,48.95 92.29,55.96 93.09,56.76
+V_CV1_PRE on BOTTOM: 72.67,51.55 73.17,52.05 73.17,55.46 74.47,56.76 77.53,56.76 81.48,52.8 84.53,52.8 88.39,56.66 89.09,56.66 89.99,57.56 89.99,58.86 89.29,59.56 89.29,60.76 89.19,60.86 74.68,60.86 68.47,54.65 68.47,51.85 68.77,51.55
+V_CV2 on BOTTOM: 88.64,39.49 91.59,36.54 99.7,36.54 101.9,34.33 101.9,33.63 101.1,32.83 86.09,32.83 85.79,33.13 85.79,36.64 84.78,37.64 84.78,38.94 85.34,39.49
+V_CV2_PRE on BOTTOM (solid shape): 71.6,37.11 71.6,36.86 74.7,36.86 74.7,32.61 71.6,32.61 71.6,32.41 70.1,32.41 70.1,37.11
+V_CV2_PRE on BOTTOM: 65.5,36.4 65.5,34.7 65.52,34.68 65.52,34.28 67.87,31.93 73.87,31.93 74.67,32.73 74.67,37.04 74.47,37.24 70.07,37.24 69.33,36.5 65.6,36.5
+V_LED on BOTTOM: 80.06,0.4 79.46,1 79.46,2.2 79.06,2.6 75.26,2.6 75.16,2.7 75.16,4.3 75.26,4.4 80.46,4.4 81.06,3.8 81.06,2.3 81.36,2 91.39,2 94.4,5.01 94.4,6.61 91.79,9.21 91.79,12.41 92.99,12.41 93.7,13.12 93.7,14.5 95.03,15.83 95.03,23.99 92.84,26.18 83.73,26.18 79.68,30.23 76.98,30.23 76.18,29.43 76.18,27.83 76.08,27.73 74.78,27.73 74.68,27.83 74.68,30.43 76.28,32.03 82.98,32.03 85.44,29.58 90.49,29.58 91.44,30.53 93.09,30.53 93.9,29.73 93.9,28.93 100.2,22.62 100.2,21.32 99.8,20.92 98,20.92 97.5,20.42 97.5,2.7 95.7,0.9 95.67,0.9 95.47,0.7 95.47,0.6 95.27,0.4
BIAS_1_TX on BOTTOM: 40.89,48.6 41.9,48.6 42.5,49.2 42.5,50.4 41.9,51 39.19,51 38.34,51.85 38.34,55.16 38.09,55.41 36.69,55.41 36.34,55.06 36.34,50.55 37.14,49.75 39.74,49.75
BIAS_2_TX on BOTTOM: 40.2,52.6 40.3,52.5 42.5,52.5 42.5,59.2 41.94,59.76 41.04,59.76 40.8,59.52 40.8,59 40.7,58.9 40.7,55.2 40.2,54.7
CV1_TX on BOTTOM (solid shape): 64.72,54.87 64.72,54.62 67.82,54.62 67.82,50.37 64.72,50.37 64.72,50.17 63.22,50.17 63.22,54.88
CV1_TX on BOTTOM (solid shape): 68.27,56.86 68.27,56.06 67.77,55.56 67.77,48.65 67.37,48.25 66.67,48.25 65.01,49.9 61.2,49.9 60.6,50.5 60.6,52.69 60.6,52.71 60.61,52.73 60.61,54.1 61.36,54.85 63.3,54.85 63.4,54.95 63.4,56.3 64.3,57.2 67.93,57.2
CV2_TX on TOP (solid shape): 64.96,39.34 68.4,39.34 69.49,38.25 69.49,37.54 68.32,36.37 63.66,36.37 62.69,37.34 60.96,37.34 60.5,37.8 60.5,41.38 61.06,41.94 62.36,41.94
CV2_TX on BOTTOM (solid shape): 62.76,41.54 62.76,37.94 62.16,37.34 61.16,37.34 60.66,37.84 60.66,41.54 61.06,41.94 62.36,41.94
D1_TX on BOTTOM: 40,31.4 38.99,32.4 37.87,32.4 37.64,32.63 37.64,34.53 37.8,34.7 41.5,34.7 43.2,33 43.2,24.4 42.9,24.1 41.2,24.1 40,25.3
LED_RTN on BOTTOM: 73.3,2.5 72.6,3.2 72.6,4.3 72.2,4.7 70.1,4.7 69.2,5.6 69.2,8.64 69.57,9.01 70.07,9.01 71.85,10.79 71.85,13.8 72.05,14 72.4,14 72.5,13.9 72.5,13.4 72.3,13.2 72.3,9.95 71,8.65 71,7.01 71.05,7.01 71.85,6.2 74.9,6.2 75.8,7.11 75.8,8.4 75.78,8.42 75.78,8.99 73.5,11.26 73.5,13.2 73.3,13.4 73.3,13.9 73.4,14 74.07,14 74.3,13.77 74.3,12.71 77.6,9.41 77.6,5.7 76.6,4.7 75,4.7 74.6,4.3 74.6,3.1 74,2.5
LED_TX on BOTTOM (solid shape): 62.86,36.24 62.86,34.73 63.2,34.4 64.86,34.4 67.98,31.28 69.12,31.28 69.67,30.73 69.67,28.13 70.27,27.53 70.35,27.52 70.39,27.51 71.66,27.51 71.7,27.52 71.75,27.53 72.57,27.53 72.62,27.52 72.66,27.51 73.93,27.51 73.97,27.52 74.02,27.53 74.7,27.53 74.75,27.52 74.79,27.51 76.06,27.51 76.1,27.52 76.15,27.53 76.28,27.53 76.68,27.93 76.68,29.23 77.28,29.83 78.28,29.83 78.93,29.18 78.93,27.28 77.98,26.33 69.37,26.33 68.97,26.73 68.17,27.53 68.17,28.4 64.36,32.2 61,32.2 60.6,32.6 60.6,36.18 61.26,36.84 62.26,36.84
LN_IN_1 on BOTTOM (solid shape): 17.1,3.3 16.1,2.3 11.5,2.3 11.4,2.4 11.4,4.2 11.5,4.3 16.1,4.3
LN_IN_1 on BOTTOM: 5,41.71 6,40.71 6,37.46 5.4,36.86 4.6,36.86 4,37.46 4,40.71
LN_IN_2 on BOTTOM (solid shape): 23.8,4.1 23.8,2.5 23.6,2.3 19.2,2.3 18.2,3.3 19.2,4.3 23.6,4.3
LN_IN_2 on TOP: 20.02,31.13 20.02,8.41 24.32,4.1 24.32,3.1 23.72,2.5 22.92,2.5 18.42,7.01 18.42,34.53 18.82,34.93 20.52,34.93 20.82,34.63 20.82,31.93
LN_IN_2 on BOTTOM: 15.62,29.03 20.52,29.03 20.72,29.23 20.72,34.53 20.42,34.83 19.12,34.83 15.62,31.33
LN_IN_3 on BOTTOM (solid shape): 24.5,14.8 24.5,13.2 24.3,13 19.9,13 18.9,14 19.9,15 24.3,15
LN_IN_3 on BOTTOM: 19.62,22.42 19.62,19.12 21.82,16.92 24.02,16.92 24.42,16.52 24.42,14.71 21.02,14.71 21.02,15.02 21.12,15.12 21.12,15.32 17.42,19.02 17.42,22.12 15.62,23.92 15.62,26.33 15.72,26.43 20.32,26.43 20.62,26.13 20.62,23.42
LN_IN_4 on BOTTOM (solid shape): 17.8,14 16.8,13 12.2,13 12.1,13.1 12.1,14.9 12.2,15 16.8,15
LN_IN_4 on BOTTOM: 13.91,16.92 12.71,16.92 12.21,16.42 12.21,13.81 12.51,13.51 14.41,13.51 15.22,14.31 15.22,15.62
LN_IN_4 on BOTTOM: 11,41.71 12,40.71 12,37.46 11.4,36.86 10.6,36.86 10,37.46 10,40.71
NEUTRAL on TOP (solid shape): 52.47,63.65 54.47,63.15 52.47,62.65 54.47,62.15 49.47,62.15 49.47,64.15 54.47,64.15
NEUTRAL on BOTTOM (solid shape): 52.48,63.66 54.48,63.16 52.48,62.66 54.48,62.16 49.48,62.16 49.48,64.16 54.48,64.16
SR_D on BOTTOM (solid shape): 67.1,46.7 67.1,42.7 66.9,42.5 63.41,42.49 63.41,46.7 66.35,46.7
SR_D on BOTTOM (solid shape): 64.76,47.1 67.07,47.1 67.24,46.92 67.24,41.77 67.97,41.04 67.97,40.6 67.57,40.2 63.9,40.2 63.34,40.77 63.34,42.04 60.7,44.68 60.7,48.65 61.1,49.05 62.81,49.05
N515201 on TOP: 80.58,38.04 79.78,37.24 77.78,37.24 77.38,37.64 77.38,43.44 75.48,45.35 75.48,45.85 76.28,46.65 77.28,46.65 80.58,43.34
N515201 on BOTTOM: 78.68,36.04 76.98,37.74 76.98,39.24 77.78,40.04 79.08,40.04 79.68,40.64 79.68,44.24 77.28,46.65 76.18,46.65 75.18,45.65 75.18,34.13 75.68,33.63 76.98,33.63 77.38,33.23 78.48,33.23 78.68,33.43
N563406 on BOTTOM: 70.37,31.23 70.37,27.93 70.47,27.83 73.97,27.83 73.97,28.93 73.87,29.03 72.37,29.03 71.87,29.53 71.87,31.03 71.67,31.23
N707266 on BOTTOM: 11,42.71 10,43.71 10,46.31 10.6,46.91 11.4,46.91 12,46.31 12,43.71
N707302 on BOTTOM: 5,42.71 4,43.71 4,46.36 4.6,46.96 5.4,46.96 6,46.36 6,43.71

Small or netless copper shapes (teardrops, artwork), in the pictures only: 3 on BOTTOM

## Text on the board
Ref Des/Silkscreen Bottom: TM | FWC | ACK | REQ | MINNO-S | MINNO-M | L | N
User.Comments: 1mm spark gap
Ref Des/Silkscreen Top: GND | ADIM | PWM | STBY | LED- | LED+ | S/N | 2015 | DER-871 | REV.B | 5V+ | 12V+ | JP1
User.14: FIGURE | FINISHED_SIZE | 12.0 | 21.0 | 29.921 | 30.0 | 31.098 | 35.0 | 35.429 | 40.0 | 40.161 | 45.98 | 50.0 | 51.969 | 59.839 | 60.0 | DRILL CHART: TOP to BOTTOM | ALL UNITS ARE IN MILS | PLATED | QTY | 41 | 106 | 4 | 16 | 2 | 30 | 12 | 8 | 6 | 18 | 259 | TOTAL HOLES:
User.16: NOTE: CUTOUT UNDER U2. | NOTES: UNLESS OTHERWISE SPECIFIED | 1.  THROUGH HOLES ARE PLATED THROUGH. | 2.  MATERIAL: BASE MATERIAL LAMINATED EPOXY | 3.  SOLDER PLATE WILL BE RoHS COMPLIANT. | 4.  SOLDER MASK LPI (LIQUID PHOTO IMAGEABLE) BOTH SIDES. COLOR GREEN. | 5.  SILKSCREEN TOP/BOTTOM SIDE. COLOR WHITE.(MIN.WIDTH 0.005" MAX.WIDTH 0.010") | 6.  FINISH TO BE SMOBC. | 7.  LEAD FREE HASL (HOT AIR SOLDER LEVEL) OR RoHS COMPLIANT. | 8.  BOARD DIMENTION +/- 0.005" | 9.  DRILL TOLERANCE+/-0.003" | 10.  TRACE WIDTH UNDER 0.010" +/- 0.002" | 11.  TRACE SPACE +/- 0.003" | 12.  MATERIAL FR4 COPPER 2 OZ TOTAL BOARD THICKNESS 0.062" | 13. 2 LAYER BOARD (COPPER ON BOTH TOP AND BOTTOM SIDES). | 14.  FAB HOUSE LOGO,DATE CODE TO BE IN SILK SCREEN ONLY.DO NOT USE COPPER. | UL APPROVED MANUFACTURED SOURCE FOR FR4. | SOLDER MASK (REGISTRATION) -0/+0.003" | TRACE WIDTH OVER 0.011" +/- 0.005"
